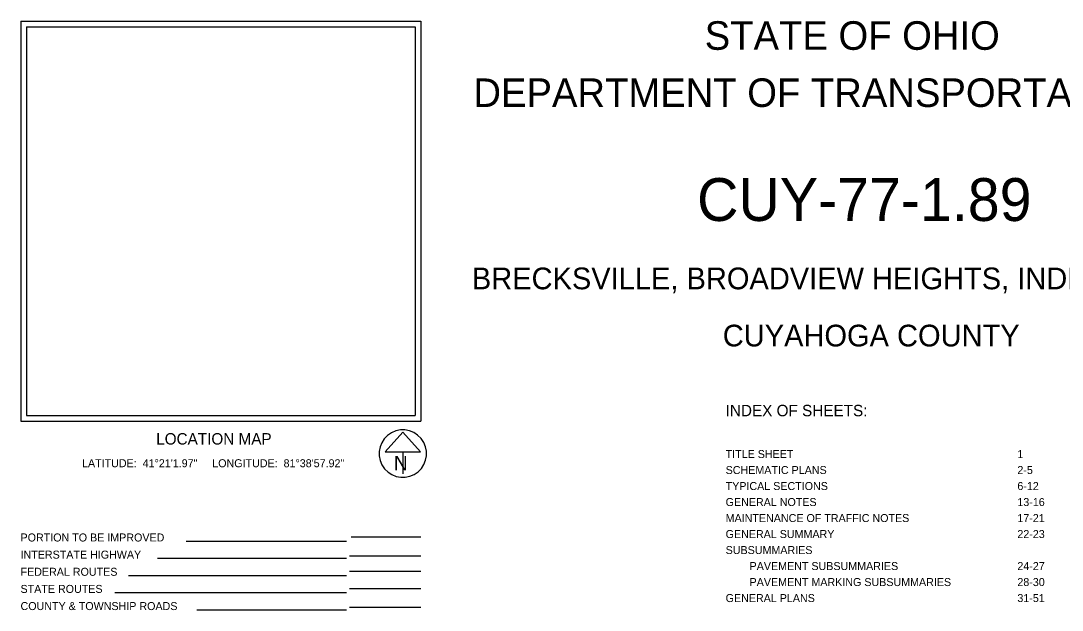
# Model space of a CAD drawing. Extents: x -17.5 to 72.9, y -57.8 to 32.3.
# Drawn here: x 1.45 to 19.67, y -37.75 to -27.44 of the extents above; entities that cross this region are included whole.
import ezdxf

# ---------------------------------------------------------------- set-up
doc = ezdxf.new("R2010")
doc.units = 0
doc.layers.add('Default', color=7, linetype='Continuous')
doc.layers.add('SH_Data', color=7, linetype='Continuous')

msp = doc.modelspace()

# ---------------------------------------------------------------- linework, layer by layer
at = {"layer": 'SH_Data'}
for p, q in [((1.445, -27.445), (8.445, -27.445)), ((1.445, -27.445), (1.445, -34.445)), ((8.445, -27.445), (8.445, -34.445)), ((1.545, -27.545), (1.545, -34.345)), ((1.545, -27.545), (8.345, -27.545)), ((8.345, -27.545), (8.345, -34.345)), ((1.545, -34.345), (8.345, -34.345)), ((1.445, -34.445), (8.445, -34.445)), ((8.13, -34.636), (7.822, -34.978)), ((8.437, -34.978), (8.13, -34.636)), ((7.822, -34.978), (8.437, -34.978)), ((8.13, -34.978), (8.13, -35.364)), ((8.13, -35.01), (8.13, -35.01)), ((8.13, -35.01), (8.13, -35.01)), ((7.145, -36.548), (4.339, -36.548)), ((7.228, -36.469), (8.445, -36.469)), ((8.445, -36.804), (7.195, -36.804)), ((7.145, -36.848), (3.835, -36.848)), ((7.145, -37.148), (3.331, -37.148)), ((8.445, -37.075), (7.195, -37.075)), ((7.145, -37.448), (3.09, -37.448)), ((8.445, -37.375), (7.195, -37.375)), ((8.445, -37.702), (7.195, -37.702)), ((7.145, -37.748), (4.523, -37.748))]:
    msp.add_line(p, q, dxfattribs=at)
msp.add_arc((8.13, -35.01), 0.415, 129.7798, 129.7633, dxfattribs=at)

# ---------------------------------------------------------------- texts
at = {"layer": 'Default'}
for s, height, p in [('STATE OF OHIO', 0.5, (13.413, -27.945)), ('DEPARTMENT OF TRANSPORTATION', 0.5, (9.365, -28.945)), ('CUY-77-1.89', 0.75, (13.279, -30.94)), ('BRECKSVILLE, BROADVIEW HEIGHTS, INDEPENDENCE', 0.38, (9.338, -32.135)), ('CUYAHOGA COUNTY', 0.38, (13.729, -33.135))]:
    msp.add_text(s, height=height, dxfattribs=at).set_placement(p)
at = {"layer": 'SH_Data'}
for s, height, p in [('INDEX OF SHEETS:', 0.2, (13.779, -34.357)), ('LOCATION MAP', 0.2, (3.814, -34.852)), ('TITLE SHEET', 0.14, (13.779, -35.088)), ('1', 0.14, (18.884, -35.088)), ('LATITUDE:  41°21\'1.97"     LONGITUDE:  81°38\'57.92"', 0.14, (2.516, -35.249)), ('N', 0.25, (7.974, -35.301)), ('SCHEMATIC PLANS', 0.14, (13.779, -35.368)), ('2-5', 0.14, (18.884, -35.368)), ('TYPICAL SECTIONS', 0.14, (13.779, -35.648)), ('6-12', 0.14, (18.884, -35.648)), ('GENERAL NOTES', 0.14, (13.779, -35.928)), ('13-16', 0.14, (18.884, -35.928)), ('MAINTENANCE OF TRAFFIC NOTES', 0.14, (13.779, -36.208)), ('17-21', 0.14, (18.884, -36.208)), ('PORTION TO BE IMPROVED', 0.14, (1.44, -36.548)), ('GENERAL SUMMARY', 0.14, (13.779, -36.488)), ('22-23', 0.14, (18.884, -36.488)), ('SUBSUMMARIES', 0.14, (13.779, -36.768)), ('INTERSTATE HIGHWAY', 0.14, (1.44, -36.848)), ('PAVEMENT SUBSUMMARIES', 0.14, (14.198, -37.048)), ('24-27', 0.14, (18.884, -37.048)), ('FEDERAL ROUTES', 0.14, (1.44, -37.148)), ('STATE ROUTES', 0.14, (1.44, -37.448)), ('PAVEMENT MARKING SUBSUMMARIES', 0.14, (14.198, -37.328)), ('28-30', 0.14, (18.884, -37.328)), ('GENERAL PLANS', 0.14, (13.779, -37.608)), ('31-51', 0.14, (18.884, -37.608)), ('COUNTY & TOWNSHIP ROADS', 0.14, (1.44, -37.748))]:
    msp.add_text(s, height=height, dxfattribs=at).set_placement(p)

doc.saveas('drawing.dxf')
